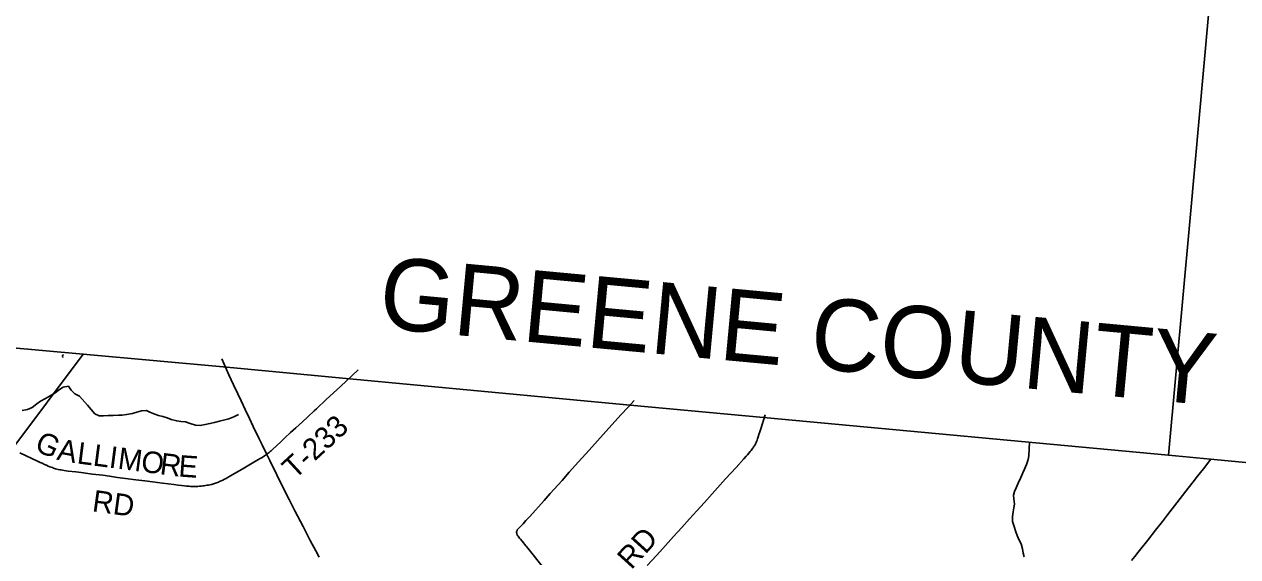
# Model space of a CAD drawing. Extents: x 1442749 to 1756758, y 235267 to 677782.
# Drawn here: x 1622634 to 1639504, y 565368 to 572767 of the extents above; entities that cross this region are included whole.
import ezdxf

# ---------------------------------------------------------------- set-up
doc = ezdxf.new("R2010")
doc.units = 0
for name, color, linetype in [('GM_X_Adjacent_County', 7, 'Continuous'), ('GM_X_Adjacent_County_Text', 7, 'Continuous'), ('GM_X_County', 7, 'Continuous'), ('GM_X_County_Road', 7, 'Continuous'), ('GM_X_County_Road_Text', 7, 'Continuous'), ('GM_X_Minor_Lake', 7, 'Continuous'), ('GM_X_Minor_River', 7, 'Continuous'), ('GM_X_State_Route', 7, 'Continuous'), ('GM_X_Township', 7, 'Continuous'), ('GM_X_Township_Road', 7, 'Continuous'), ('GM_X_Township_Road_Text', 7, 'Continuous')]:
    doc.layers.add(name, color=color, linetype=linetype)

msp = doc.modelspace()

# ---------------------------------------------------------------- linework, layer by layer
at = {"layer": 'GM_X_Adjacent_County'}
for points in [[(1622375, 568282), (1623453, 568184), (1625400, 568006), (1627110, 567846), (1631058, 567476), (1632910, 567303), (1638543, 566777), (1638842, 570076), (1639097, 572897), (1639456, 576867), (1639791, 580666), (1640135, 584378), (1640197, 585063), (1640696, 590579)], [(1652040, 565503), (1651277, 565574), (1641608, 566488), (1639127, 566722), (1638543, 566777), (1638842, 570076), (1639097, 572897), (1639456, 576867), (1639791, 580666), (1640135, 584378), (1640197, 585063), (1640696, 590579)]]:
    msp.add_lwpolyline(points, dxfattribs=at)
at = {"layer": 'GM_X_County'}
msp.add_lwpolyline([(1622375, 568282), (1623453, 568184), (1625400, 568006), (1627110, 567846), (1631058, 567476), (1632910, 567303), (1638543, 566777), (1639127, 566722), (1641608, 566488), (1651277, 565574), (1652040, 565503)], dxfattribs=at)
at = {"layer": 'GM_X_County_Road'}
msp.add_lwpolyline([(1622574, 566811), (1622828, 566691), (1622854, 566679), (1622881, 566666), (1622914, 566651), (1622943, 566638), (1622967, 566628), (1622990, 566619), (1623007, 566612), (1623024, 566606), (1623039, 566600), (1623052, 566596), (1623070, 566591), (1623087, 566586), (1623107, 566581), (1623127, 566577), (1623146, 566573), (1623165, 566570), (1623187, 566567), (1623214, 566563), (1623246, 566559), (1623351, 566547), (1623427, 566537), (1623517, 566526), (1623582, 566517), (1623725, 566499), (1623819, 566486), (1623930, 566471), (1624039, 566457), (1624184, 566438), (1624309, 566422), (1624418, 566408), (1624556, 566391), (1624713, 566370), (1624773, 566362), (1624819, 566356), (1624860, 566352), (1624887, 566349), (1624910, 566348), (1624928, 566347), (1624947, 566346), (1624964, 566346), (1624983, 566345), (1625003, 566345), (1625026, 566346), (1625049, 566346), (1625069, 566348), (1625092, 566350), (1625115, 566352), (1625136, 566355), (1625154, 566358), (1625174, 566361), (1625193, 566364), (1625215, 566369), (1625236, 566373), (1625250, 566377), (1625264, 566381), (1625292, 566389), (1625306, 566395), (1625322, 566400), (1625336, 566406), (1625349, 566411), (1625372, 566421), (1625394, 566432), (1625416, 566444), (1625441, 566457), (1625470, 566473), (1625501, 566491), (1625685, 566600), (1625801, 566668), (1625906, 566729), (1625932, 566744), (1625955, 566758), (1625973, 566769), (1625988, 566779), (1626005, 566790)], dxfattribs=at)
at = {"layer": 'GM_X_Minor_Lake'}
msp.add_lwpolyline([(1623169, 568138), (1623167, 568157), (1623170, 568167), (1623181, 568176)], dxfattribs=at)
at = {"layer": 'GM_X_Minor_River'}
for points in [[(1622604, 567400), (1622678, 567416), (1622743, 567443), (1622810, 567493), (1622860, 567530), (1622931, 567566), (1622994, 567603), (1623063, 567643), (1623125, 567691), (1623176, 567726), (1623247, 567736), (1623284, 567681), (1623336, 567632), (1623400, 567598), (1623515, 567472), (1623563, 567415), (1623615, 567355), (1623677, 567324), (1623733, 567327), (1623801, 567331), (1623870, 567332), (1623942, 567336), (1623997, 567337), (1624057, 567344), (1624140, 567360), (1624200, 567377), (1624263, 567395), (1624331, 567402), (1624381, 567376), (1624451, 567349), (1624501, 567332), (1624562, 567316), (1624622, 567297), (1624678, 567276), (1624754, 567256), (1624810, 567249), (1624874, 567242), (1624941, 567220)], [(1624941, 567220), (1625015, 567195), (1625079, 567190), (1625150, 567206), (1625214, 567217), (1625279, 567233), (1625349, 567252), (1625422, 567270), (1625478, 567285), (1625547, 567311), (1625614, 567344)], [(1636536, 565366), (1636522, 565418), (1636513, 565477), (1636493, 565545), (1636466, 565598), (1636436, 565664), (1636417, 565715), (1636395, 565787), (1636372, 565858), (1636374, 565928), (1636383, 565990), (1636390, 566048), (1636398, 566100), (1636391, 566173), (1636384, 566225), (1636398, 566275), (1636423, 566327), (1636452, 566389), (1636487, 566469), (1636517, 566533), (1636540, 566585), (1636567, 566651), (1636588, 566719), (1636600, 566771), (1636609, 566961)]]:
    msp.add_lwpolyline(points, dxfattribs=at)
at = {"layer": 'GM_X_State_Route'}
msp.add_lwpolyline([(1626732, 565362), (1626686, 565449), (1626610, 565595), (1626509, 565790), (1626397, 566005), (1626316, 566163), (1626271, 566250), (1626143, 566505), (1626047, 566703), (1626005, 566790), (1625940, 566925), (1625900, 567007), (1625818, 567179), (1625765, 567288), (1625705, 567415), (1625648, 567534), (1625602, 567631), (1625544, 567756), (1625479, 567897), (1625379, 568117)], dxfattribs=at)
at = {"layer": 'GM_X_Township'}
for points in [[(1576704, 554811), (1576814, 555881), (1577349, 561102), (1577745, 564960), (1578438, 571717), (1578513, 572449), (1579838, 572308), (1580857, 572200), (1588468, 571492), (1591507, 571209), (1594558, 570925), (1600110, 570408), (1601218, 570299), (1605315, 569892), (1608125, 569657), (1616080, 568853), (1618534, 568633), (1622375, 568282), (1623453, 568184), (1622446, 566839), (1615321, 557320), (1613178, 554457)], [(1613178, 554457), (1615321, 557320), (1622446, 566839), (1623453, 568184), (1625400, 568006), (1627110, 567846), (1631058, 567476), (1632910, 567303), (1638543, 566777), (1639127, 566722), (1641608, 566488), (1651277, 565574), (1652040, 565503)]]:
    msp.add_lwpolyline(points, dxfattribs=at)
at = {"layer": 'GM_X_Township_Road'}
for points in [[(1626005, 566790), (1626012, 566796), (1626025, 566806), (1626038, 566817), (1626054, 566831), (1626065, 566841), (1626078, 566851), (1626205, 566970), (1626258, 567019), (1626337, 567093), (1626409, 567159), (1626501, 567243), (1626576, 567312), (1626662, 567393), (1626695, 567424), (1626832, 567552), (1627029, 567735), (1627275, 567963)], [(1629866, 565196), (1629709, 565394), (1629635, 565486), (1629614, 565511), (1629606, 565521), (1629554, 565585), (1629533, 565610), (1629518, 565628), (1629510, 565639), (1629500, 565652), (1629496, 565658), (1629491, 565665), (1629488, 565672), (1629485, 565677), (1629483, 565683), (1629481, 565690), (1629480, 565696), (1629479, 565703), (1629479, 565709), (1629479, 565714), (1629480, 565721), (1629483, 565728), (1629485, 565733), (1629488, 565740), (1629492, 565745), (1629497, 565751), (1629502, 565757), (1629508, 565765), (1629568, 565826), (1629608, 565870), (1629661, 565928), (1629860, 566151), (1629947, 566248), (1630110, 566429), (1630211, 566541), (1630341, 566688), (1630487, 566848), (1630526, 566892), (1630603, 566977), (1630762, 567152), (1630934, 567342), (1631024, 567441), (1631114, 567539)], [(1631293, 565244), (1631423, 565387), (1631509, 565482), (1631624, 565608), (1631661, 565649), (1631718, 565713), (1631776, 565776), (1631883, 565895), (1631982, 566004), (1632089, 566120), (1632196, 566240), (1632270, 566324), (1632382, 566448), (1632531, 566610), (1632637, 566727), (1632669, 566763), (1632687, 566784), (1632707, 566807), (1632725, 566828), (1632739, 566845), (1632750, 566860), (1632760, 566873), (1632767, 566883), (1632774, 566894), (1632782, 566905), (1632788, 566916), (1632793, 566925), (1632800, 566937), (1632808, 566954), (1632813, 566967), (1632822, 566988), (1632827, 567004), (1632832, 567019), (1632837, 567035), (1632847, 567066), (1632858, 567102), (1632872, 567145), (1632935, 567338)], [(1638029, 565316), (1638071, 565369), (1638120, 565431), (1638252, 565598), (1638362, 565737), (1638457, 565858), (1638527, 565949), (1638560, 565991), (1638624, 566073), (1638815, 566319), (1638883, 566408), (1638946, 566488), (1639026, 566588), (1639131, 566723)]]:
    msp.add_lwpolyline(points, dxfattribs=at)

# ---------------------------------------------------------------- texts
at = {"layer": 'GM_X_Adjacent_County_Text'}
msp.add_text('GREENE COUNTY', height=1000, rotation=354.6648, dxfattribs=at).set_placement((1627540, 568551))
at = {"layer": 'GM_X_County_Road_Text'}
for s, rotation, p in [('G', 335.0692, (1622761, 566855)), ('A', 348.9284, (1623076, 566719)), ('L', 352.769, (1623357, 566665)), ('L', 352.6342, (1623579, 566636)), ('I', 352.6466, (1623802, 566608)), ('M', 352.6372, (1623924, 566592)), ('O', 352.636, (1624247, 566550)), ('R', 352.7425, (1624509, 566516)), ('E', 355.8083, (1624771, 566483)), ('RD', 352.2813, (1623568, 566000))]:
    msp.add_text(s, height=300, rotation=rotation, dxfattribs=at).set_placement(p)
at = {"layer": 'GM_X_Township_Road_Text'}
for s, rotation, p in [('T-233', 42.6486, (1626392, 566432)), ('RD', 47.7597, (1631073, 565178))]:
    msp.add_text(s, height=300, rotation=rotation, dxfattribs=at).set_placement(p)

doc.saveas('drawing.dxf')
